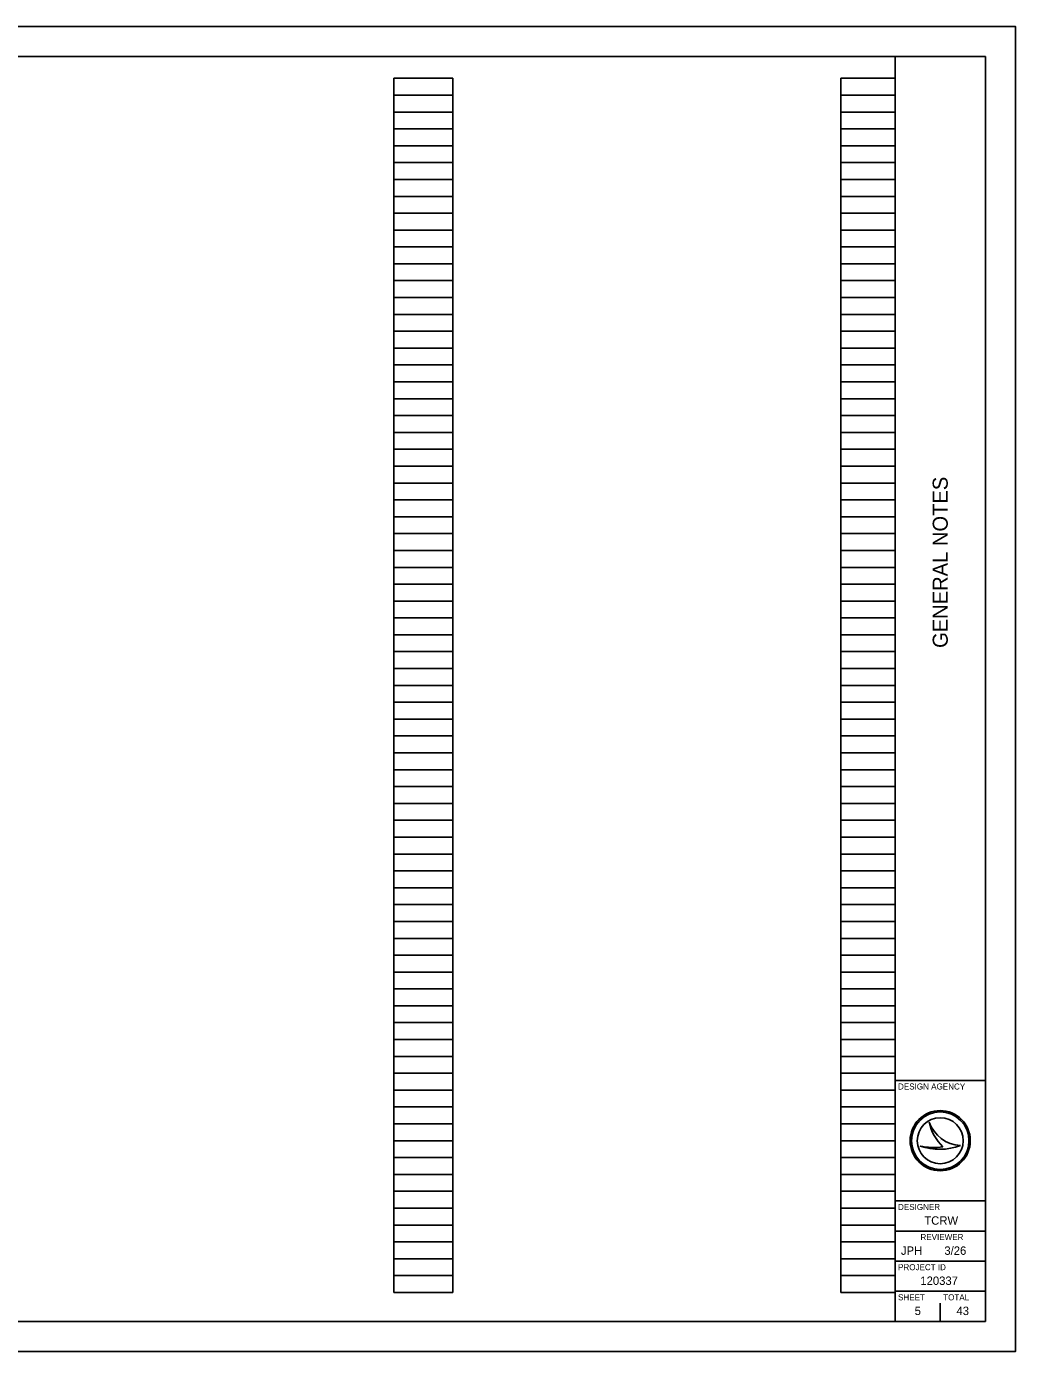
# Model space of a CAD drawing. Extents: x 0 to 34, y 0 to 22.
# Drawn here: x 17.58 to 34, y 0 to 22 of the extents above; entities that cross this region are included whole.
import ezdxf

# ---------------------------------------------------------------- set-up
doc = ezdxf.new("R2010")
doc.units = 0
for name, color, linetype in [('SH_Border', 7, 'Continuous'), ('SH_Cut_Line', 7, 'Continuous'), ('SH_Data', 7, 'Continuous')]:
    doc.layers.add(name, color=color, linetype=linetype)

msp = doc.modelspace()

# ---------------------------------------------------------------- linework, layer by layer
at = {"layer": 'SH_Border'}
for p, q in [((32, 0.5), (32, 21.5)), ((32, 4.5), (33.5, 4.5)), ((32, 2.5), (33.5, 2.5)), ((32, 2), (33.5, 2)), ((32, 1.5), (33.5, 1.5)), ((32, 1), (33.5, 1))]:
    msp.add_line(p, q, dxfattribs=at)
msp.add_lwpolyline([(1.5, 21.5), (33.5, 21.5), (33.5, 0.5), (1.5, 0.5)], close=True, dxfattribs=at)
at = {"layer": 'SH_Cut_Line'}
msp.add_lwpolyline([(0, 0), (34, 0), (34, 22), (0, 22)], close=True, dxfattribs=at)
at = {"layer": 'SH_Data'}
for p, q in [((23.68, 0.98), (23.68, 21.14)), ((23.68, 21.14), (24.66, 21.14)), ((24.66, 0.98), (24.66, 21.14)), ((31.1, 0.98), (31.1, 21.14)), ((31.1, 21.14), (32, 21.14)), ((32, 0.98), (32, 21.14)), ((23.68, 20.86), (24.66, 20.86)), ((31.1, 20.86), (32, 20.86)), ((23.68, 20.58), (24.66, 20.58)), ((31.1, 20.58), (32, 20.58)), ((23.68, 20.3), (24.66, 20.3)), ((31.1, 20.3), (32, 20.3)), ((23.68, 20.02), (24.66, 20.02)), ((31.1, 20.02), (32, 20.02)), ((23.68, 19.74), (24.66, 19.74)), ((31.1, 19.74), (32, 19.74)), ((23.68, 19.46), (24.66, 19.46)), ((31.1, 19.46), (32, 19.46)), ((23.68, 19.18), (24.66, 19.18)), ((31.1, 19.18), (32, 19.18)), ((23.68, 18.9), (24.66, 18.9)), ((31.1, 18.9), (32, 18.9)), ((23.68, 18.62), (24.66, 18.62)), ((31.1, 18.62), (32, 18.62)), ((23.68, 18.34), (24.66, 18.34)), ((31.1, 18.34), (32, 18.34)), ((23.68, 18.06), (24.66, 18.06)), ((31.1, 18.06), (32, 18.06)), ((23.68, 17.78), (24.66, 17.78)), ((31.1, 17.78), (32, 17.78)), ((23.68, 17.5), (24.66, 17.5)), ((31.1, 17.5), (32, 17.5)), ((23.68, 17.22), (24.66, 17.22)), ((31.1, 17.22), (32, 17.22)), ((23.68, 16.94), (24.66, 16.94)), ((31.1, 16.94), (32, 16.94)), ((23.68, 16.66), (24.66, 16.66)), ((31.1, 16.66), (32, 16.66)), ((23.68, 16.38), (24.66, 16.38)), ((31.1, 16.38), (32, 16.38)), ((23.68, 16.1), (24.66, 16.1)), ((31.1, 16.1), (32, 16.1)), ((23.68, 15.82), (24.66, 15.82)), ((31.1, 15.82), (32, 15.82)), ((23.68, 15.54), (24.66, 15.54)), ((31.1, 15.54), (32, 15.54)), ((23.68, 15.26), (24.66, 15.26)), ((31.1, 15.26), (32, 15.26)), ((23.68, 14.98), (24.66, 14.98)), ((31.1, 14.98), (32, 14.98)), ((23.68, 14.7), (24.66, 14.7)), ((31.1, 14.7), (32, 14.7)), ((23.68, 14.42), (24.66, 14.42)), ((31.1, 14.42), (32, 14.42)), ((23.68, 14.14), (24.66, 14.14)), ((31.1, 14.14), (32, 14.14)), ((23.68, 13.86), (24.66, 13.86)), ((31.1, 13.86), (32, 13.86)), ((23.68, 13.58), (24.66, 13.58)), ((31.1, 13.58), (32, 13.58)), ((23.68, 13.3), (24.66, 13.3)), ((31.1, 13.3), (32, 13.3)), ((23.68, 13.02), (24.66, 13.02)), ((31.1, 13.02), (32, 13.02)), ((23.68, 12.74), (24.66, 12.74)), ((31.1, 12.74), (32, 12.74)), ((23.68, 12.46), (24.66, 12.46)), ((31.1, 12.46), (32, 12.46)), ((23.68, 12.18), (24.66, 12.18)), ((31.1, 12.18), (32, 12.18)), ((23.68, 11.9), (24.66, 11.9)), ((31.1, 11.9), (32, 11.9)), ((23.68, 11.62), (24.66, 11.62)), ((31.1, 11.62), (32, 11.62)), ((23.68, 11.34), (24.66, 11.34)), ((31.1, 11.34), (32, 11.34)), ((23.68, 11.06), (24.66, 11.06)), ((31.1, 11.06), (32, 11.06)), ((23.68, 10.78), (24.66, 10.78)), ((31.1, 10.78), (32, 10.78)), ((23.68, 10.5), (24.66, 10.5)), ((31.1, 10.5), (32, 10.5)), ((23.68, 10.22), (24.66, 10.22)), ((31.1, 10.22), (32, 10.22)), ((23.68, 9.94), (24.66, 9.94)), ((31.1, 9.94), (32, 9.94)), ((23.68, 9.66), (24.66, 9.66)), ((31.1, 9.66), (32, 9.66)), ((23.68, 9.38), (24.66, 9.38)), ((31.1, 9.38), (32, 9.38)), ((23.68, 9.1), (24.66, 9.1)), ((31.1, 9.1), (32, 9.1)), ((23.68, 8.82), (24.66, 8.82)), ((31.1, 8.82), (32, 8.82)), ((23.68, 8.54), (24.66, 8.54)), ((31.1, 8.54), (32, 8.54)), ((23.68, 8.26), (24.66, 8.26)), ((31.1, 8.26), (32, 8.26)), ((23.68, 7.98), (24.66, 7.98)), ((31.1, 7.98), (32, 7.98)), ((23.68, 7.7), (24.66, 7.7)), ((31.1, 7.7), (32, 7.7)), ((23.68, 7.42), (24.66, 7.42)), ((31.1, 7.42), (32, 7.42)), ((23.68, 7.14), (24.66, 7.14)), ((31.1, 7.14), (32, 7.14)), ((23.68, 6.86), (24.66, 6.86)), ((31.1, 6.86), (32, 6.86)), ((23.68, 6.58), (24.66, 6.58)), ((31.1, 6.58), (32, 6.58)), ((23.68, 6.3), (24.66, 6.3)), ((31.1, 6.3), (32, 6.3)), ((23.68, 6.02), (24.66, 6.02)), ((31.1, 6.02), (32, 6.02)), ((23.68, 5.74), (24.66, 5.74)), ((31.1, 5.74), (32, 5.74)), ((23.68, 5.46), (24.66, 5.46)), ((31.1, 5.46), (32, 5.46)), ((23.68, 5.18), (24.66, 5.18)), ((31.1, 5.18), (32, 5.18)), ((23.68, 4.9), (24.66, 4.9)), ((31.1, 4.9), (32, 4.9)), ((23.68, 4.62), (24.66, 4.62)), ((31.1, 4.62), (32, 4.62)), ((23.68, 4.34), (24.66, 4.34)), ((31.1, 4.34), (32, 4.34)), ((23.68, 4.06), (24.66, 4.06)), ((31.1, 4.06), (32, 4.06)), ((23.68, 3.78), (24.66, 3.78)), ((31.1, 3.78), (32, 3.78)), ((32.567, 3.81), (32.567, 3.81)), ((23.68, 3.5), (24.66, 3.5)), ((31.1, 3.5), (32, 3.5)), ((32.417, 3.41), (32.417, 3.41)), ((32.75, 3.5), (32.75, 3.5)), ((33.087, 3.419), (33.087, 3.419)), ((23.68, 3.22), (24.66, 3.22)), ((31.1, 3.22), (32, 3.22)), ((23.68, 2.94), (24.66, 2.94)), ((31.1, 2.94), (32, 2.94)), ((23.68, 2.66), (24.66, 2.66)), ((31.1, 2.66), (32, 2.66)), ((23.68, 2.38), (24.66, 2.38)), ((31.1, 2.38), (32, 2.38)), ((23.68, 2.1), (24.66, 2.1)), ((31.1, 2.1), (32, 2.1)), ((23.68, 1.82), (24.66, 1.82)), ((31.1, 1.82), (32, 1.82)), ((23.68, 1.54), (24.66, 1.54)), ((31.1, 1.54), (32, 1.54)), ((23.68, 1.26), (24.66, 1.26)), ((31.1, 1.26), (32, 1.26)), ((23.68, 0.98), (24.66, 0.98)), ((31.1, 0.98), (32, 0.98)), ((32.375, 0.675), (32.375, 0.675)), ((32.75, 0.5), (32.75, 0.8))]:
    msp.add_line(p, q, dxfattribs=at)
for radius in [0.5, 0.477, 0.477, 0.382]:
    msp.add_circle((32.75, 3.5), radius, dxfattribs=at)
for centre, radius, start, end in [((33.116, 3.998), 0.58, 198.9257, 198.9319), ((33.347, 3.97), 0.796, 191.6379, 191.6421), ((33.116, 3.998), 0.58, 198.9319, 267.1657), ((33.347, 3.97), 0.796, 191.6421, 226.0947), ((32.739, 4.37), 1.013, 251.4576, 290.0832), ((32.648, 4.654), 1.266, 259.4964, 259.4995), ((32.739, 4.37), 1.013, 251.4527, 251.4576), ((32.648, 4.654), 1.266, 259.4995, 276.6672)]:
    msp.add_arc(centre, radius, start, end, dxfattribs=at)

# ---------------------------------------------------------------- texts
msp.add_text('GENERAL NOTES', height=0.25, rotation=90, dxfattribs=at).set_placement((32.875, 11.682))
for s, height, p in [('DESIGN AGENCY', 0.1, (32.05, 4.35)), ('DESIGNER', 0.1, (32.05, 2.35)), ('TCRW', 0.14, (32.486, 2.105)), ('REVIEWER', 0.1, (32.422, 1.85)), ('JPH', 0.14, (32.098, 1.605)), ('3/26', 0.14, (32.819, 1.605)), ('PROJECT ID', 0.1, (32.05, 1.35)), ('120337', 0.14, (32.42, 1.105)), ('SHEET', 0.1, (32.05, 0.85)), ('TOTAL', 0.1, (32.8, 0.85)), ('5', 0.14, (32.326, 0.605)), ('43', 0.14, (33.02, 0.605))]:
    msp.add_text(s, height=height, dxfattribs=at).set_placement(p)

doc.saveas('drawing.dxf')
